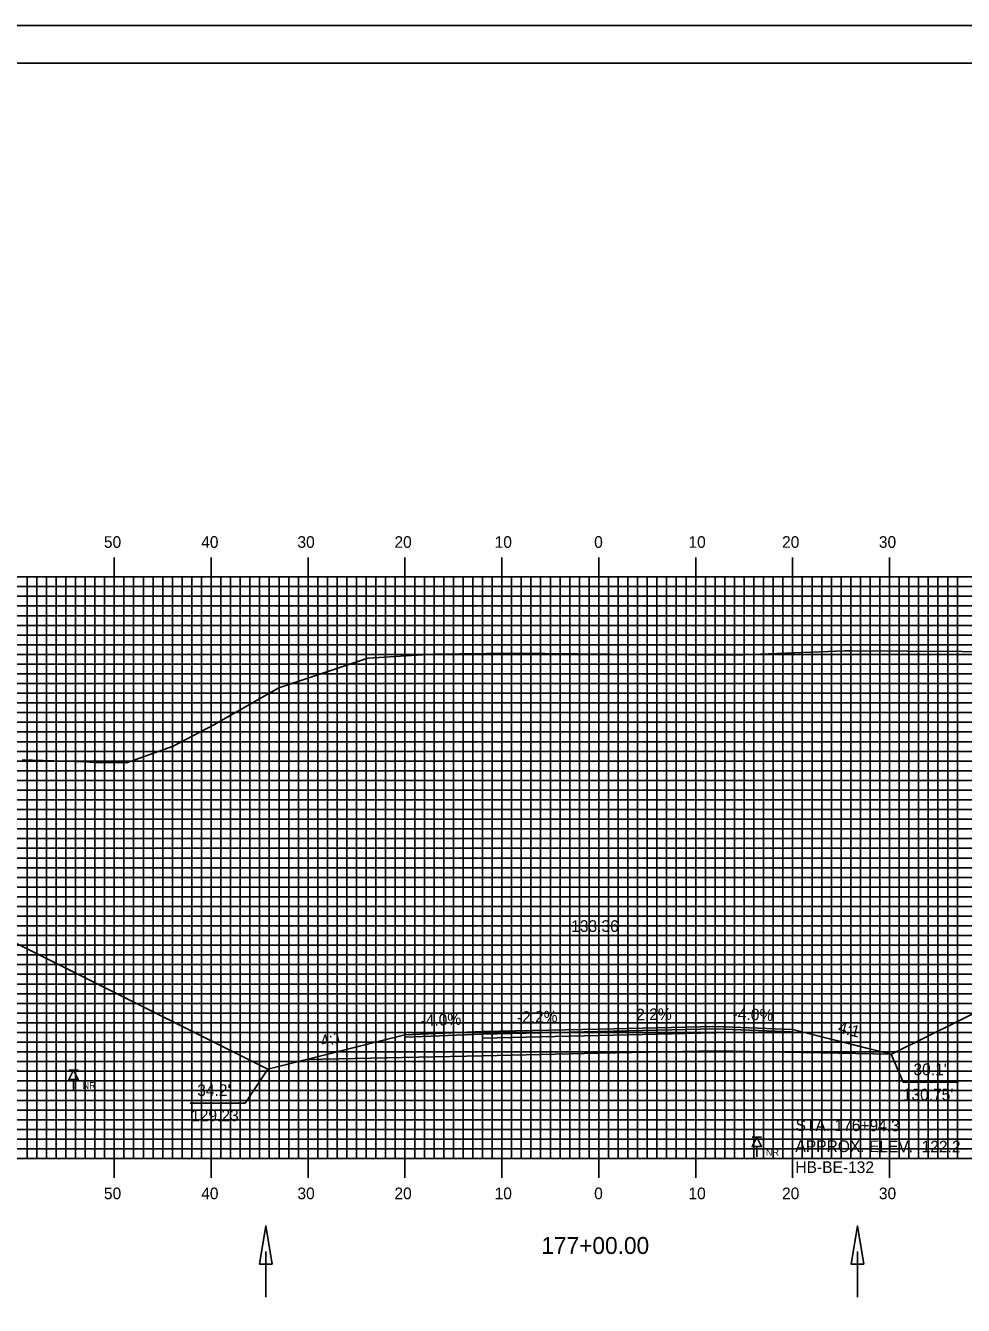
# Model space of a CAD drawing. Extents: x 1784615 to 1784958, y 442591 to 442811.
# Drawn here: x 1784721.4 to 1784818.1, y 442678.5 to 442810.5 of the extents above; entities that cross this region are included whole.
import ezdxf

# ---------------------------------------------------------------- set-up
doc = ezdxf.new("R2010")
doc.units = 0
for name, color, linetype in [('ANNOTATION', 7, 'Continuous'), ('BORDER', 7, 'Continuous'), ('BORING - NO REFUSAL', 7, 'Continuous'), ('D_Drainage_Ditch_Line', 7, 'Continuous'), ('D_Roadway_Centerline', 7, 'Continuous'), ('D_Roadway_Centerline_Text', 7, 'Continuous'), ('D_Roadway_Edge_Shoulder', 7, 'Continuous'), ('D_Roadway_Edge_TW', 7, 'Continuous'), ('D_Roadway_Pavement', 7, 'Continuous'), ('D_Roadway_SlopeLines', 7, 'Continuous'), ('D_Roadway_SubGrade', 7, 'Continuous'), ('H_V ANNOTATION', 7, 'Continuous'), ('MAJOR', 7, 'Continuous'), ('MINOR', 7, 'Continuous'), ('PLOT BOUNDARY', 7, 'Continuous'), ('S_Roadway_Centerline', 7, 'Continuous')]:
    doc.layers.add(name, color=color, linetype=linetype)

msp = doc.modelspace()

# ---------------------------------------------------------------- linework, layer by layer
at = {"layer": 'ANNOTATION'}
for points in [[(1784817.62, 442701.53), (1784811.92, 442701.53), (1784810.69, 442704.42)], [(1784738.33, 442699.39), (1784744.02, 442699.39), (1784746.34, 442702.89)]]:
    msp.add_lwpolyline(points, dxfattribs=at)
at = {"layer": 'BORDER'}
msp.add_lwpolyline([(1784630.91, 442596.67), (1784950.91, 442596.67), (1784950.91, 442806.67), (1784630.91, 442806.67)], close=True, dxfattribs=at)
at = {"layer": 'BORING - NO REFUSAL'}
for p, q in [((1784726.79, 442702.77), (1784725.83, 442702.77)), ((1784726.31, 442701.81), (1784726.31, 442700.75)), ((1784797.29, 442695.87), (1784796.33, 442695.87)), ((1784796.81, 442694.91), (1784796.81, 442693.85))]:
    msp.add_line(p, q, dxfattribs=at)
for points in [[(1784726.31, 442702.77), (1784726.79, 442701.81), (1784725.83, 442701.81)], [(1784796.81, 442695.87), (1784797.29, 442694.91), (1784796.33, 442694.91)]]:
    msp.add_lwpolyline(points, close=True, dxfattribs=at)
at = {"layer": 'D_Drainage_Ditch_Line'}
for p, q in [((1784746.14, 442684.08), (1784746.14, 442679.38)), ((1784807.2, 442684.08), (1784807.2, 442679.38))]:
    msp.add_line(p, q, dxfattribs=at)
for points in [[(1784746.79, 442682.77), (1784745.48, 442682.77), (1784746.14, 442686.71)], [(1784807.86, 442682.77), (1784806.54, 442682.77), (1784807.2, 442686.71)]]:
    msp.add_lwpolyline(points, close=True, dxfattribs=at)
at = {"layer": 'D_Roadway_Edge_Shoulder'}
for points in [[(1784768.51, 442706.76), (1784760.51, 442706.44), (1784760.51, 442706.19), (1784768.51, 442706.51)], [(1784792.51, 442707.29), (1784800.51, 442706.97), (1784800.51, 442706.72), (1784792.51, 442707.04)]]:
    msp.add_lwpolyline(points, close=True, dxfattribs=at)
at = {"layer": 'D_Roadway_Edge_TW'}
msp.add_lwpolyline([(1784768.51, 442706.51), (1784768.51, 442706.76), (1784780.51, 442707.02), (1784792.51, 442707.29), (1784792.51, 442707.04), (1784780.51, 442706.77)], close=True, dxfattribs=at)
at = {"layer": 'D_Roadway_Pavement'}
msp.add_lwpolyline([(1784768.51, 442706.09), (1784768.51, 442706.51), (1784780.51, 442706.77), (1784792.51, 442707.04), (1784792.51, 442706.62), (1784780.51, 442706.35)], close=True, dxfattribs=at)
at = {"layer": 'D_Roadway_SlopeLines'}
msp.add_line((1784810.7, 442704.42), (1784889.7, 442743.74), dxfattribs=at)
for points in [[(1784746.34, 442702.89), (1784686.14, 442732.99), (1784684.89, 442733.53), (1784683.64, 442733.91), (1784682.39, 442734.11), (1784681.14, 442734.14)], [(1784760.51, 442706.44), (1784746.34, 442702.89)], [(1784800.51, 442706.97), (1784808.55, 442704.96)]]:
    msp.add_lwpolyline(points, dxfattribs=at)
at = {"layer": 'D_Roadway_SubGrade'}
msp.add_lwpolyline([(1784768.51, 442704.26), (1784750.34, 442703.89), (1784760.51, 442706.44), (1784760.51, 442706.19), (1784768.51, 442706.51), (1784780.51, 442706.77), (1784792.51, 442707.04), (1784800.51, 442706.72), (1784800.51, 442706.97), (1784810.69, 442704.42), (1784792.51, 442704.79), (1784780.51, 442704.52)], close=True, dxfattribs=at)
at = {"layer": 'MAJOR'}
for p, q in [((1784730.51, 442755.67), (1784730.51, 442753.67)), ((1784740.51, 442755.67), (1784740.51, 442753.67)), ((1784750.51, 442755.67), (1784750.51, 442753.67)), ((1784760.51, 442755.67), (1784760.51, 442753.67)), ((1784770.51, 442755.67), (1784770.51, 442753.67)), ((1784780.51, 442755.67), (1784780.51, 442753.67)), ((1784790.51, 442755.67), (1784790.51, 442753.67)), ((1784800.51, 442755.67), (1784800.51, 442753.67)), ((1784810.51, 442755.67), (1784810.51, 442753.67)), ((1784640.51, 442753.67), (1784920.51, 442753.67)), ((1784640.51, 442753.67), (1784920.51, 442753.67)), ((1784730.51, 442693.67), (1784730.51, 442753.67)), ((1784740.51, 442693.67), (1784740.51, 442753.67)), ((1784750.51, 442693.67), (1784750.51, 442753.67)), ((1784760.51, 442693.67), (1784760.51, 442753.67)), ((1784770.51, 442693.67), (1784770.51, 442753.67)), ((1784780.51, 442693.67), (1784780.51, 442753.67)), ((1784790.51, 442693.67), (1784790.51, 442753.67)), ((1784800.51, 442693.67), (1784800.51, 442753.67)), ((1784810.51, 442693.67), (1784810.51, 442753.67)), ((1784640.51, 442748.67), (1784920.51, 442748.67)), ((1784640.51, 442743.67), (1784920.51, 442743.67)), ((1784640.51, 442738.67), (1784920.51, 442738.67)), ((1784640.51, 442733.67), (1784920.51, 442733.67)), ((1784640.51, 442728.67), (1784920.51, 442728.67)), ((1784640.51, 442723.67), (1784920.51, 442723.67)), ((1784640.51, 442718.67), (1784920.51, 442718.67)), ((1784640.51, 442713.67), (1784920.51, 442713.67)), ((1784640.51, 442708.67), (1784920.51, 442708.67)), ((1784640.51, 442703.67), (1784920.51, 442703.67)), ((1784640.51, 442698.67), (1784920.51, 442698.67)), ((1784640.51, 442693.67), (1784920.51, 442693.67)), ((1784640.51, 442693.67), (1784920.51, 442693.67)), ((1784730.51, 442691.66), (1784730.51, 442693.67)), ((1784740.51, 442691.66), (1784740.51, 442693.67)), ((1784750.51, 442691.66), (1784750.51, 442693.67)), ((1784760.51, 442691.66), (1784760.51, 442693.67)), ((1784770.51, 442691.66), (1784770.51, 442693.67)), ((1784780.51, 442691.66), (1784780.51, 442693.67)), ((1784790.51, 442691.66), (1784790.51, 442693.67)), ((1784800.51, 442691.66), (1784800.51, 442693.67)), ((1784810.51, 442691.66), (1784810.51, 442693.67))]:
    msp.add_line(p, q, dxfattribs=at)
at = {"layer": 'MINOR'}
for p, q in [((1784721.51, 442693.67), (1784721.51, 442753.67)), ((1784722.51, 442693.67), (1784722.51, 442753.67)), ((1784723.51, 442693.67), (1784723.51, 442753.67)), ((1784724.51, 442693.67), (1784724.51, 442753.67)), ((1784725.51, 442693.67), (1784725.51, 442753.67)), ((1784726.51, 442693.67), (1784726.51, 442753.67)), ((1784727.51, 442693.67), (1784727.51, 442753.67)), ((1784728.51, 442693.67), (1784728.51, 442753.67)), ((1784729.51, 442693.67), (1784729.51, 442753.67)), ((1784731.51, 442693.67), (1784731.51, 442753.67)), ((1784732.51, 442693.67), (1784732.51, 442753.67)), ((1784733.51, 442693.67), (1784733.51, 442753.67)), ((1784734.51, 442693.67), (1784734.51, 442753.67)), ((1784735.51, 442693.67), (1784735.51, 442753.67)), ((1784736.51, 442693.67), (1784736.51, 442753.67)), ((1784737.51, 442693.67), (1784737.51, 442753.67)), ((1784738.51, 442693.67), (1784738.51, 442753.67)), ((1784739.51, 442693.67), (1784739.51, 442753.67)), ((1784741.51, 442693.67), (1784741.51, 442753.67)), ((1784742.51, 442693.67), (1784742.51, 442753.67)), ((1784743.51, 442693.67), (1784743.51, 442753.67)), ((1784744.51, 442693.67), (1784744.51, 442753.67)), ((1784745.51, 442693.67), (1784745.51, 442753.67)), ((1784746.51, 442693.67), (1784746.51, 442753.67)), ((1784747.51, 442693.67), (1784747.51, 442753.67)), ((1784748.51, 442693.67), (1784748.51, 442753.67)), ((1784749.51, 442693.67), (1784749.51, 442753.67)), ((1784751.51, 442693.67), (1784751.51, 442753.67)), ((1784752.51, 442693.67), (1784752.51, 442753.67)), ((1784753.51, 442693.67), (1784753.51, 442753.67)), ((1784754.51, 442693.67), (1784754.51, 442753.67)), ((1784755.51, 442693.67), (1784755.51, 442753.67)), ((1784756.51, 442693.67), (1784756.51, 442753.67)), ((1784757.51, 442693.67), (1784757.51, 442753.67)), ((1784758.51, 442693.67), (1784758.51, 442753.67)), ((1784759.51, 442693.67), (1784759.51, 442753.67)), ((1784761.51, 442693.67), (1784761.51, 442753.67)), ((1784762.51, 442693.67), (1784762.51, 442753.67)), ((1784763.51, 442693.67), (1784763.51, 442753.67)), ((1784764.51, 442693.67), (1784764.51, 442753.67)), ((1784765.51, 442693.67), (1784765.51, 442753.67)), ((1784766.51, 442693.67), (1784766.51, 442753.67)), ((1784767.51, 442693.67), (1784767.51, 442753.67)), ((1784768.51, 442693.67), (1784768.51, 442753.67)), ((1784769.51, 442693.67), (1784769.51, 442753.67)), ((1784771.51, 442693.67), (1784771.51, 442753.67)), ((1784772.51, 442693.67), (1784772.51, 442753.67)), ((1784773.51, 442693.67), (1784773.51, 442753.67)), ((1784774.51, 442693.67), (1784774.51, 442753.67)), ((1784775.51, 442693.67), (1784775.51, 442753.67)), ((1784776.51, 442693.67), (1784776.51, 442753.67)), ((1784777.51, 442693.67), (1784777.51, 442753.67)), ((1784778.51, 442693.67), (1784778.51, 442753.67)), ((1784779.51, 442693.67), (1784779.51, 442753.67)), ((1784781.51, 442693.67), (1784781.51, 442753.67)), ((1784782.51, 442693.67), (1784782.51, 442753.67)), ((1784783.51, 442693.67), (1784783.51, 442753.67)), ((1784784.51, 442693.67), (1784784.51, 442753.67)), ((1784785.51, 442693.67), (1784785.51, 442753.67)), ((1784786.51, 442693.67), (1784786.51, 442753.67)), ((1784787.51, 442693.67), (1784787.51, 442753.67)), ((1784788.51, 442693.67), (1784788.51, 442753.67)), ((1784789.51, 442693.67), (1784789.51, 442753.67)), ((1784791.51, 442693.67), (1784791.51, 442753.67)), ((1784792.51, 442693.67), (1784792.51, 442753.67)), ((1784793.51, 442693.67), (1784793.51, 442753.67)), ((1784794.51, 442693.67), (1784794.51, 442753.67)), ((1784795.51, 442693.67), (1784795.51, 442753.67)), ((1784796.51, 442693.67), (1784796.51, 442753.67)), ((1784797.51, 442693.67), (1784797.51, 442753.67)), ((1784798.51, 442693.67), (1784798.51, 442753.67)), ((1784799.51, 442693.67), (1784799.51, 442753.67)), ((1784801.51, 442693.67), (1784801.51, 442753.67)), ((1784802.51, 442693.67), (1784802.51, 442753.67)), ((1784803.51, 442693.67), (1784803.51, 442753.67)), ((1784804.51, 442693.67), (1784804.51, 442753.67)), ((1784805.51, 442693.67), (1784805.51, 442753.67)), ((1784806.51, 442693.67), (1784806.51, 442753.67)), ((1784807.51, 442693.67), (1784807.51, 442753.67)), ((1784808.51, 442693.67), (1784808.51, 442753.67)), ((1784809.51, 442693.67), (1784809.51, 442753.67)), ((1784811.51, 442693.67), (1784811.51, 442753.67)), ((1784812.51, 442693.67), (1784812.51, 442753.67)), ((1784813.51, 442693.67), (1784813.51, 442753.67)), ((1784814.51, 442693.67), (1784814.51, 442753.67)), ((1784815.51, 442693.67), (1784815.51, 442753.67)), ((1784816.51, 442693.67), (1784816.51, 442753.67)), ((1784817.51, 442693.67), (1784817.51, 442753.67)), ((1784640.51, 442752.67), (1784920.51, 442752.67)), ((1784640.51, 442751.67), (1784920.51, 442751.67)), ((1784640.51, 442750.67), (1784920.51, 442750.67)), ((1784640.51, 442749.67), (1784920.51, 442749.67)), ((1784640.51, 442747.67), (1784920.51, 442747.67)), ((1784640.51, 442746.67), (1784920.51, 442746.67)), ((1784640.51, 442745.67), (1784920.51, 442745.67)), ((1784640.51, 442744.67), (1784920.51, 442744.67)), ((1784640.51, 442742.67), (1784920.51, 442742.67)), ((1784640.51, 442741.67), (1784920.51, 442741.67)), ((1784640.51, 442740.67), (1784920.51, 442740.67)), ((1784640.51, 442739.67), (1784920.51, 442739.67)), ((1784640.51, 442737.67), (1784920.51, 442737.67)), ((1784640.51, 442736.67), (1784920.51, 442736.67)), ((1784640.51, 442735.67), (1784920.51, 442735.67)), ((1784640.51, 442734.67), (1784920.51, 442734.67)), ((1784640.51, 442732.67), (1784920.51, 442732.67)), ((1784640.51, 442731.67), (1784920.51, 442731.67)), ((1784640.51, 442730.67), (1784920.51, 442730.67)), ((1784640.51, 442729.67), (1784920.51, 442729.67)), ((1784640.51, 442727.67), (1784920.51, 442727.67)), ((1784640.51, 442726.67), (1784920.51, 442726.67)), ((1784640.51, 442725.67), (1784920.51, 442725.67)), ((1784640.51, 442724.67), (1784920.51, 442724.67)), ((1784640.51, 442722.67), (1784920.51, 442722.67)), ((1784640.51, 442721.67), (1784920.51, 442721.67)), ((1784640.51, 442720.67), (1784920.51, 442720.67)), ((1784640.51, 442719.67), (1784920.51, 442719.67)), ((1784640.51, 442717.67), (1784920.51, 442717.67)), ((1784640.51, 442716.67), (1784920.51, 442716.67)), ((1784640.51, 442715.67), (1784920.51, 442715.67)), ((1784640.51, 442714.67), (1784920.51, 442714.67)), ((1784640.51, 442712.67), (1784920.51, 442712.67)), ((1784640.51, 442711.67), (1784920.51, 442711.67)), ((1784640.51, 442710.67), (1784920.51, 442710.67)), ((1784640.51, 442709.67), (1784920.51, 442709.67)), ((1784640.51, 442707.67), (1784920.51, 442707.67)), ((1784640.51, 442706.67), (1784920.51, 442706.67)), ((1784640.51, 442705.67), (1784920.51, 442705.67)), ((1784640.51, 442704.67), (1784920.51, 442704.67)), ((1784640.51, 442702.67), (1784920.51, 442702.67)), ((1784640.51, 442701.67), (1784920.51, 442701.67)), ((1784640.51, 442700.67), (1784920.51, 442700.67)), ((1784640.51, 442699.67), (1784920.51, 442699.67)), ((1784640.51, 442697.67), (1784920.51, 442697.67)), ((1784640.51, 442696.67), (1784920.51, 442696.67)), ((1784640.51, 442695.67), (1784920.51, 442695.67)), ((1784640.51, 442694.67), (1784920.51, 442694.67))]:
    msp.add_line(p, q, dxfattribs=at)
at = {"layer": 'PLOT BOUNDARY'}
msp.add_lwpolyline([(1784614.73, 442590.55), (1784954.73, 442590.55), (1784954.73, 442810.55), (1784614.73, 442810.55)], close=True, dxfattribs=at)
at = {"layer": 'S_Roadway_Centerline'}
msp.add_lwpolyline([(1784721.01, 442734.79), (1784727.48, 442734.59), (1784728.42, 442734.54), (1784731.78, 442734.49), (1784736.58, 442736.2), (1784740.78, 442738.42), (1784747.48, 442742.23), (1784756.66, 442745.3), (1784763.46, 442745.71), (1784771.59, 442745.81), (1784785.07, 442745.68), (1784794.47, 442745.59), (1784805.94, 442746.04), (1784806.67, 442746.04), (1784818.02, 442745.99), (1784829.82, 442745.75)], dxfattribs=at)

# ---------------------------------------------------------------- texts
at = {"layer": 'ANNOTATION'}
for s, rotation, p in [('-2.2%', 1.2603, (1784772.07, 442707.64)), ('2.2%', 1.2603, (1784784.39, 442707.91)), ('-4.0%', 357.7094, (1784794.3, 442708.02)), ('-4.0%', 2.2906, (1784762.14, 442707.3)), ('4:1', 345.9638, (1784805.11, 442706.68)), ('4:1', 14.0362, (1784751.96, 442705.16))]:
    msp.add_text(s, height=1.2, rotation=rotation, dxfattribs=at).set_placement(p)
for s, p in [("30.1'", (1784812.98, 442702.26)), ("34.2'", (1784739.07, 442700.12)), ("130.75'", (1784811.88, 442699.66)), ('129.23', (1784738.44, 442697.52))]:
    msp.add_text(s, height=1.2, dxfattribs=at).set_placement(p)
at = {"layer": 'BORING - NO REFUSAL'}
for p in [(1784727.25, 442700.85), (1784797.75, 442693.95)]:
    msp.add_text('NR', height=0.7, dxfattribs=at).set_placement(p)
for s, p in [('STA. 176+94.3', (1784800.81, 442696.51)), ('APPROX. ELEV.  122.2', (1784800.8, 442694.35)), ('HB-BE-132', (1784800.79, 442692.19))]:
    msp.add_text(s, height=1.2, rotation=359.8142, dxfattribs=at).set_placement(p)
at = {"layer": 'D_Roadway_Centerline'}
for s, p in [('C', (1784780.51, 442707.02)), ('L', (1784780.51, 442707.01))]:
    msp.add_text(s, height=0.0146, dxfattribs=at).set_placement(p)
at = {"layer": 'D_Roadway_Centerline_Text'}
msp.add_text('133.36', height=1.2, dxfattribs=at).set_placement((1784777.66, 442717.05))
at = {"layer": 'H_V ANNOTATION'}
for s, height, p in [('50', 1.2, (1784729.44, 442756.67)), ('40', 1.2, (1784739.48, 442756.67)), ('30', 1.2, (1784749.41, 442756.67)), ('20', 1.2, (1784759.42, 442756.67)), ('10', 1.2, (1784769.76, 442756.67)), ('0', 1.2, (1784780.03, 442756.67)), ('10', 1.2, (1784789.76, 442756.67)), ('20', 1.2, (1784799.42, 442756.67)), ('30', 1.2, (1784809.41, 442756.67)), ('50', 1.2, (1784729.44, 442689.47)), ('40', 1.2, (1784739.48, 442689.47)), ('30', 1.2, (1784749.41, 442689.47)), ('20', 1.2, (1784759.42, 442689.47)), ('10', 1.2, (1784769.76, 442689.47)), ('0', 1.2, (1784780.03, 442689.47)), ('10', 1.2, (1784789.76, 442689.47)), ('20', 1.2, (1784799.42, 442689.47)), ('30', 1.2, (1784809.41, 442689.47)), ('177+00.00', 1.75, (1784774.58, 442683.82))]:
    msp.add_text(s, height=height, dxfattribs=at).set_placement(p)

doc.saveas('drawing.dxf')
